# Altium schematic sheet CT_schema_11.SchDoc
size 677 x 458 mm
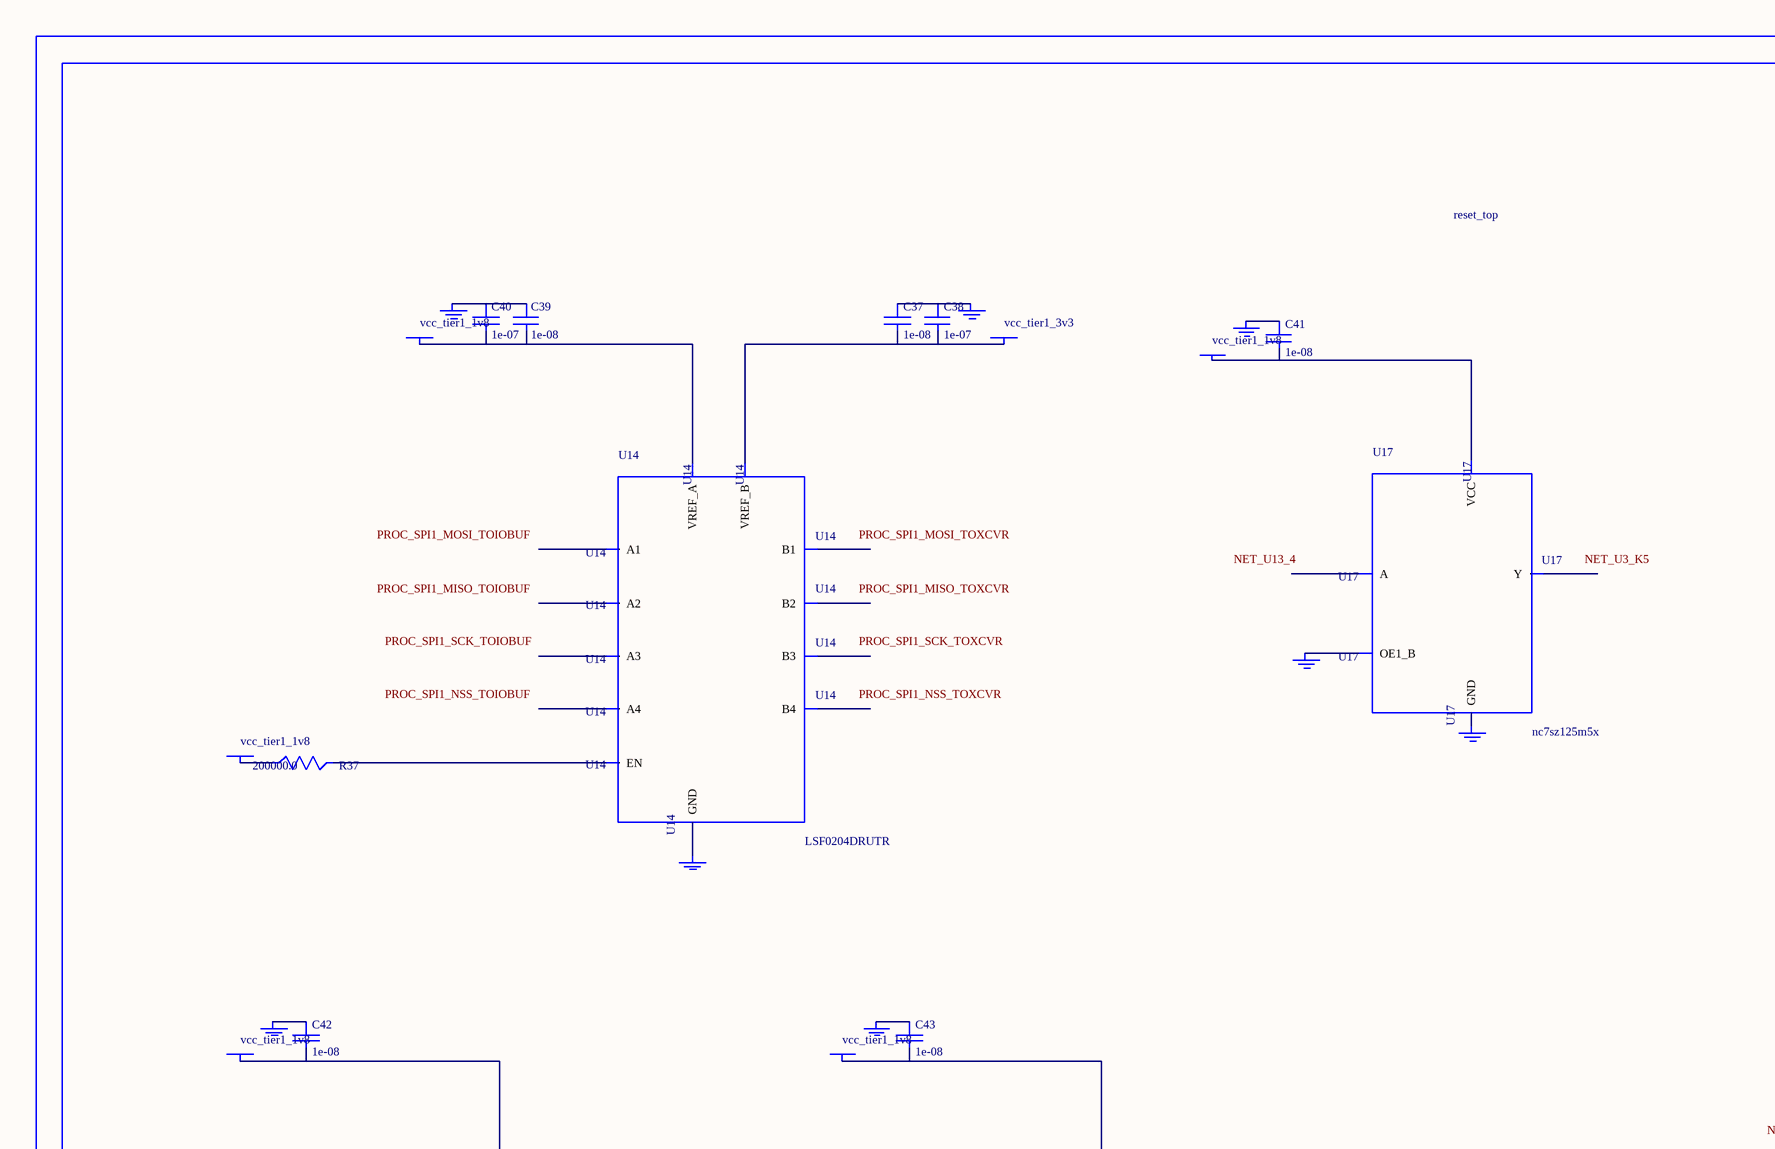
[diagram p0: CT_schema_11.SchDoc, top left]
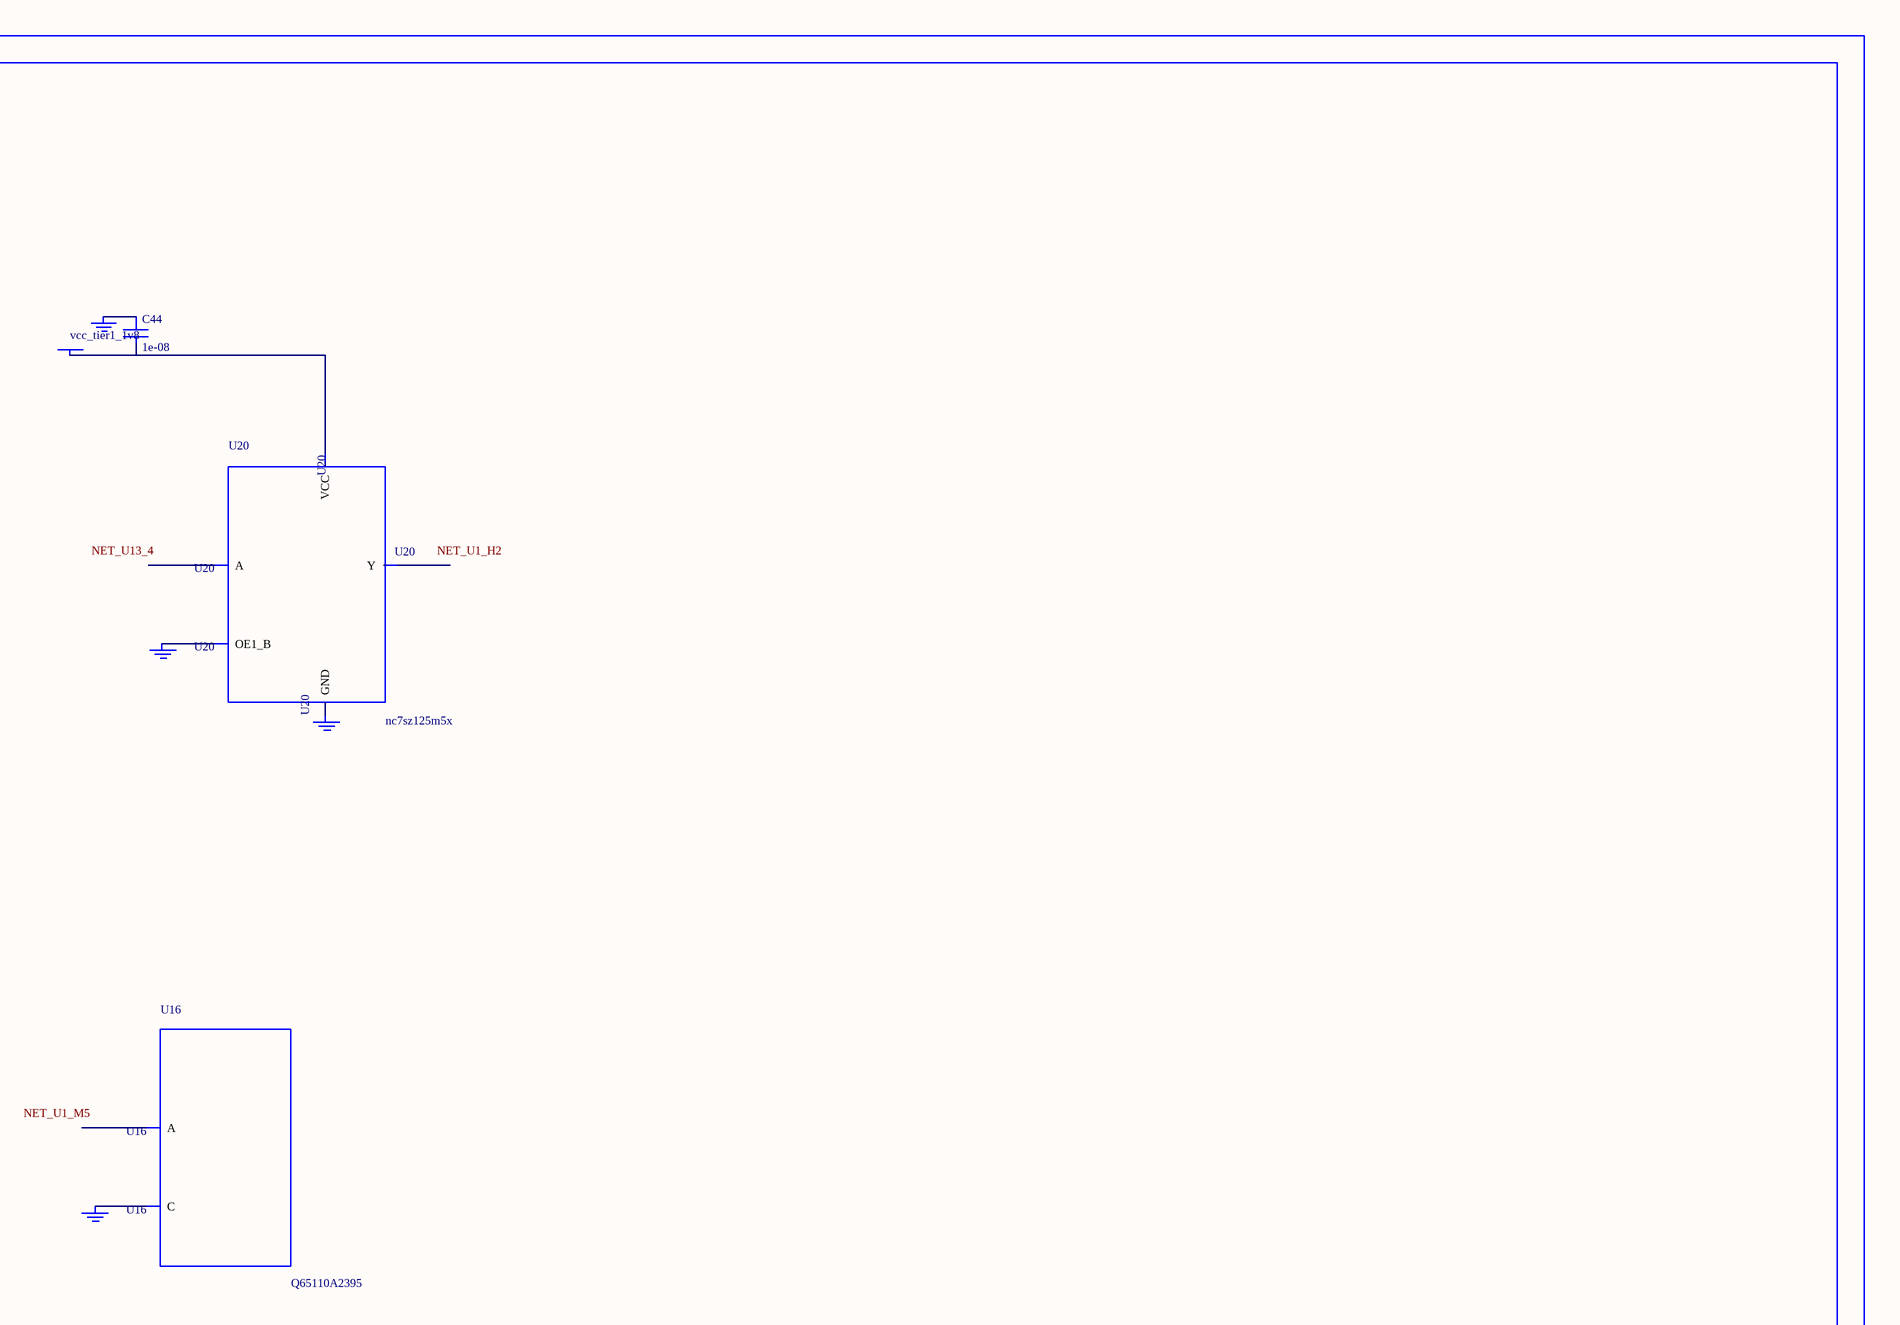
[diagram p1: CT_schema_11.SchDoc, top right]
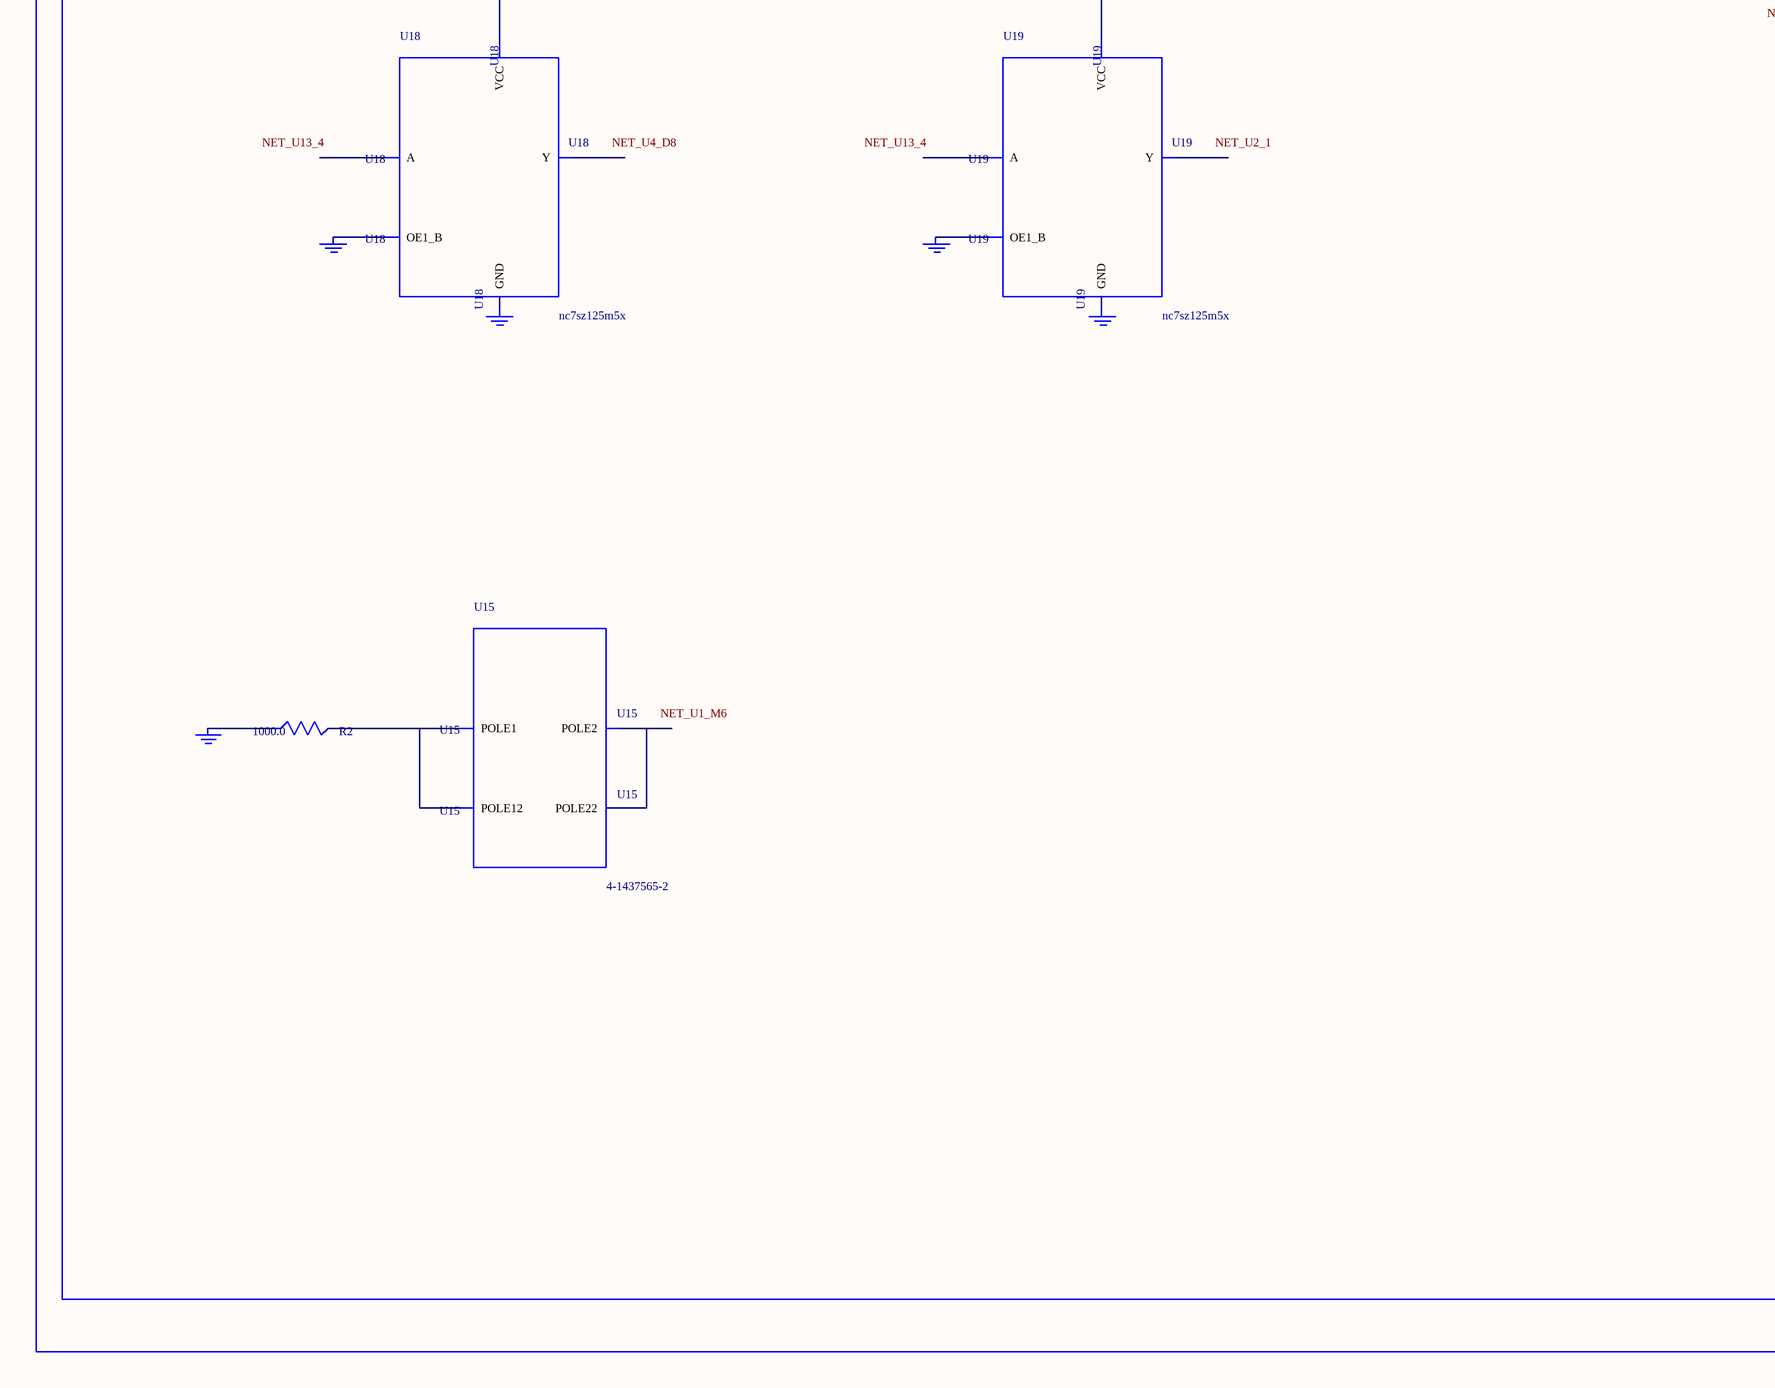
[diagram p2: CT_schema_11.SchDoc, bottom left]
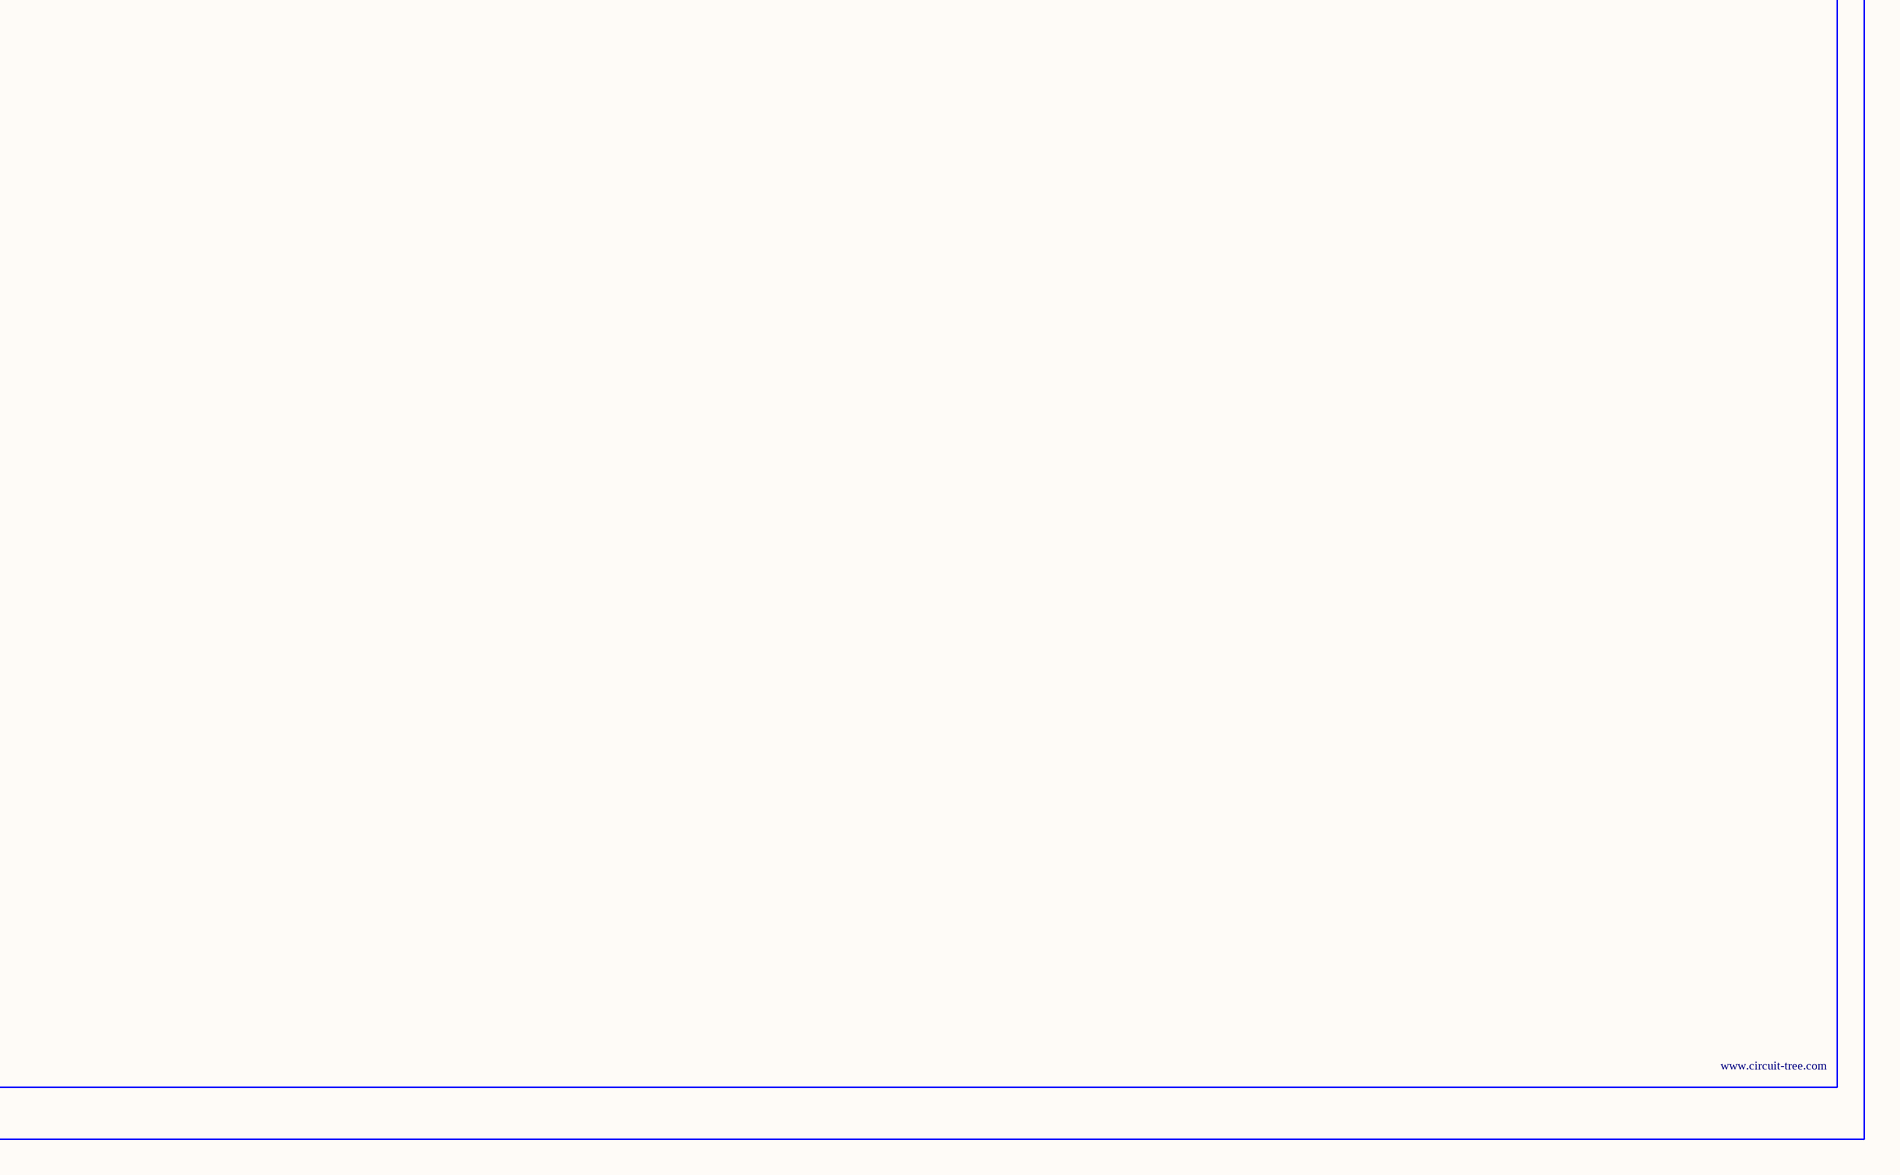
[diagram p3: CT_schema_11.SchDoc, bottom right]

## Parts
BORDER10  (no value)
C37  1e-08  [C0402]
C38  1e-07  [C0402]
C39  1e-08  [C0402]
C40  1e-07  [C0402]
C41  1e-08  [C0402]
C42  1e-08  [C0402]
C43  1e-08  [C0402]
C44  1e-08  [C0402]
GND_INSTANCE_10_0  (no value)
GND_INSTANCE_10_1  (no value)
GND_INSTANCE_10_2  (no value)
GND_INSTANCE_10_3  (no value)
GND_INSTANCE_10_4  (no value)
GND_INSTANCE_10_5  (no value)
GND_INSTANCE_10_6  (no value)
GND_INSTANCE_10_7  (no value)
GND_INSTANCE_10_8  (no value)
GND_INSTANCE_10_9  (no value)
GND_INSTANCE_10_10  (no value)
GND_INSTANCE_10_11  (no value)
GND_INSTANCE_10_12  (no value)
GND_INSTANCE_10_13  (no value)
GND_INSTANCE_10_14  (no value)
GND_INSTANCE_10_15  (no value)
GND_INSTANCE_10_16  (no value)
POWER_INSTANCE_10_0  vcc_tier1_1v8
POWER_INSTANCE_10_1  vcc_tier1_3v3
POWER_INSTANCE_10_2  vcc_tier1_1v8
POWER_INSTANCE_10_3  vcc_tier1_1v8
POWER_INSTANCE_10_4  vcc_tier1_1v8
POWER_INSTANCE_10_5  vcc_tier1_1v8
POWER_INSTANCE_10_6  vcc_tier1_1v8
R2  1000.0  [R0603]
R37  200000.0  [R0603]
U14  LSF0204DRUTR  [RUT0012A]
U15  4-1437565-2  [SW_4-1437565-2]
U16  Q65110A2395  [LGM67K-G1J2-24-Z]
U17  nc7sz125m5x  [NC7SZ125M5X]
U18  nc7sz125m5x  [NC7SZ125M5X]
U19  nc7sz125m5x  [NC7SZ125M5X]
U20  nc7sz125m5x  [NC7SZ125M5X]

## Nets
NetC37_1: C37.1 C38.1 GND_INSTANCE_10_1.0(GND)
NetC37_2: C37.2 C38.2 POWER_INSTANCE_10_1.0(PWR) U14.11(VREF_B)
NetC39_1: C39.1 C40.1 GND_INSTANCE_10_0.0(GND)
NetC39_2: C39.2 C40.2 POWER_INSTANCE_10_0.0(PWR) U14.1(VREF_A)
NetC41_1: C41.1 GND_INSTANCE_10_5.0(GND)
NetC41_2: C41.2 POWER_INSTANCE_10_3.0(PWR) U17.5(VCC)
NetC42_1: C42.1 GND_INSTANCE_10_8.0(GND)
NetC42_2: C42.2 POWER_INSTANCE_10_4.0(PWR) U18.5(VCC)
NetC43_1: C43.1 GND_INSTANCE_10_11.0(GND)
NetC43_2: C43.2 POWER_INSTANCE_10_5.0(PWR) U19.5(VCC)
NetC44_1: C44.1 GND_INSTANCE_10_14.0(GND)
NetC44_2: C44.2 POWER_INSTANCE_10_6.0(PWR) U20.5(VCC)
NetGND_INSTANCE_10_2_0: GND_INSTANCE_10_2.0(GND) U14.6(GND)
NetGND_INSTANCE_10_3_0: GND_INSTANCE_10_3.0(GND) R2.1
NetGND_INSTANCE_10_4_0: GND_INSTANCE_10_4.0(GND) U16.C
NetGND_INSTANCE_10_6_0: GND_INSTANCE_10_6.0(GND) U17.1(OE1_B)
NetGND_INSTANCE_10_7_0: GND_INSTANCE_10_7.0(GND) U17.3(GND)
NetGND_INSTANCE_10_9_0: GND_INSTANCE_10_9.0(GND) U18.1(OE1_B)
NetGND_INSTANCE_10_10_0: GND_INSTANCE_10_10.0(GND) U18.3(GND)
NetGND_INSTANCE_10_12_0: GND_INSTANCE_10_12.0(GND) U19.1(OE1_B)
NetGND_INSTANCE_10_13_0: GND_INSTANCE_10_13.0(GND) U19.3(GND)
NetGND_INSTANCE_10_15_0: GND_INSTANCE_10_15.0(GND) U20.1(OE1_B)
NetGND_INSTANCE_10_16_0: GND_INSTANCE_10_16.0(GND) U20.3(GND)
NetPOWER_INSTANCE_10_2_0: POWER_INSTANCE_10_2.0(PWR) R37.1
NetR2_2: R2.2 U15.1(POLE1) U15.2(POLE12)
NetR37_2: R37.2 U14.12(EN)
NetU15_3: U15.3(POLE2) U15.4(POLE22)

Not connected (* = marked no-connect by the designer): U14 2(A1) 3(A2) 4(A3) 5(A4) 7(B4) 8(B3) 9(B2) 10(B1); U16 A; U17 2(A) 4(Y); U18 2(A) 4(Y); U19 2(A) 4(Y); U20 2(A) 4(Y)

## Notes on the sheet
- Labels drawn without touching a wire or pin: NET_U1_H2, NET_U1_M5, NET_U1_M6, NET_U2_1, NET_U3_K5, NET_U4_D8, NET_U13_4, PROC_SPI1_MISO_TOIOBUF, PROC_SPI1_MISO_TOXCVR, PROC_SPI1_MOSI_TOIOBUF, PROC_SPI1_MOSI_TOXCVR, PROC_SPI1_NSS_TOIOBUF, PROC_SPI1_NSS_TOXCVR, PROC_SPI1_SCK_TOIOBUF, PROC_SPI1_SCK_TOXCVR

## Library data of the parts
BORDER10 = BORDER_PAGE10
C37 C39 C41-C44 = C0402C103K3RAC
C38 C40 = C0402C104K3RACTU
GND_INSTANCE_10_0-GND_INSTANCE_10_16 = GND
POWER_INSTANCE_10_0-POWER_INSTANCE_10_6 = PWR
R2 = RC0603JR-071KL
R37 = RC0603JR-07200KL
